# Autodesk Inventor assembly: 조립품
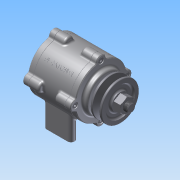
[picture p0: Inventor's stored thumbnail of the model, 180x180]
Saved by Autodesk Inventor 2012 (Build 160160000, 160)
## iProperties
Created: 2015-03
Part Number: 조립품
Document SubType Name: Assembly
Designer: net
Author: net
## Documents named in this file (11)
- C:\Users\net\Desktop\450305V1049\조립품.iam
- C:\Users\net\Documents\Inventor\450305V1049\본체.ipt
- C:\Users\net\Desktop\450305V1049\커버.ipt
- C:\Users\net\Desktop\450305V1049\커버2.ipt
- C:\Users\net\Desktop\450305V1049\M 4 x 12.ipt
- C:\Users\net\Desktop\450305V1049\V벨트풀리.ipt
- C:\Users\net\Desktop\450305V1049\너트 M12x1.25.ipt
- C:\Users\net\Desktop\450305V1049\베어링 6204.ipt
- C:\Users\net\Desktop\450305V1049\오일실.ipt
- C:\Users\net\Desktop\450305V1049\축.ipt
- C:\Users\net\Desktop\450305V1049\키(4 x 4 x 12).ipt
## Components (14 placed, 6 different names)
1. 그루브 풀리1:1
2. KS B 1012 클래스 1 일반 - 미터 M12x1.25:1
3. KS B 2804 D D - 20 32 8:1
4. KS B 1311 (I) 4 x 4 x 12:1
5. KS B 2023 6204 - 20 x 47 x 14:1
6. KS B 2023 6204 - 20 x 47 x 14:2
7. KS B 1003 - 미터 M 4 x 12:2
8. KS B 1003 - 미터 M 4 x 12:3
9. KS B 1003 - 미터 M 4 x 12:4
10. KS B 1003 - 미터 M 4 x 12:5
11. KS B 1003 - 미터 M 4 x 12:1
12. KS B 1003 - 미터 M 4 x 12:6
13. KS B 1003 - 미터 M 4 x 12:7
14. KS B 1003 - 미터 M 4 x 12:8
